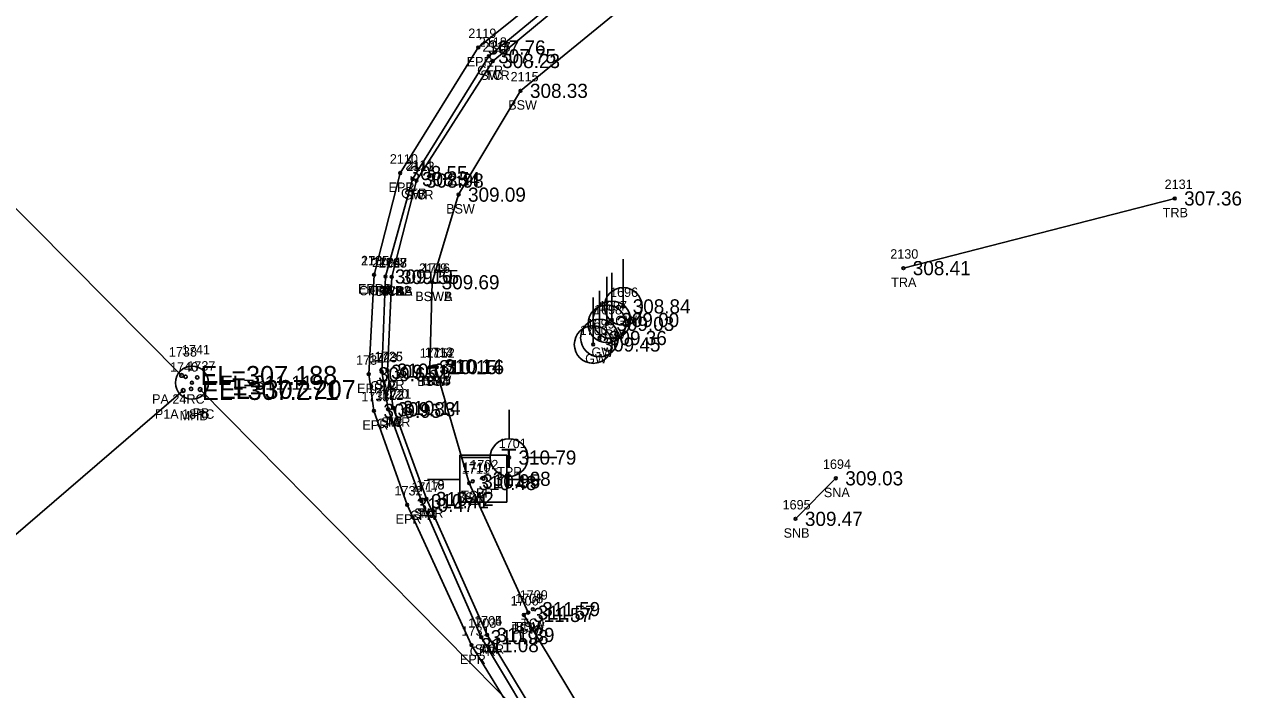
# Model space of a CAD drawing. Extents: x 1970076 to 1971136, y 803126 to 804215.
# Drawn here: x 1970647.9 to 1970777.2, y 803516.5 to 803587.1 of the extents above; entities that cross this region are included whole.
import ezdxf

# ---------------------------------------------------------------- set-up
doc = ezdxf.new("R2010")
doc.units = 0
for name, color, linetype in [('RD_EX_BldgApp', 7, 'Continuous'), ('RD_EX_BldgApp_txCode', 7, 'Continuous'), ('RD_EX_Conc', 7, 'Continuous'), ('RD_EX_Conc_txCode', 7, 'Continuous'), ('RD_EX_DR_Inlet', 7, 'Continuous'), ('RD_EX_DR_Inlet_txCode', 7, 'Continuous'), ('RD_EX_DR_Pipe', 7, 'Continuous'), ('RD_EX_DR_Pipe_txCode', 7, 'Continuous'), ('RD_EX_Road', 7, 'Continuous'), ('RD_EX_Road_txCode', 7, 'Continuous'), ('RD_EX_TX_BldgApp_ELEV', 7, 'Continuous'), ('RD_EX_TX_Conc_ELEV', 7, 'Continuous'), ('RD_EX_TX_DR_Inlet_ELEV', 7, 'Continuous'), ('RD_EX_TX_Road_ELEV', 7, 'Continuous'), ('RD_EX_TX_UT_ELEV', 7, 'Continuous'), ('RD_EX_TX_VEG_ELEV', 7, 'Continuous'), ('RD_EX_UT', 7, 'Continuous'), ('RD_EX_UT_txCode', 7, 'Continuous'), ('RD_EX_VEG', 7, 'Continuous'), ('RD_EX_VEG_txCode', 7, 'Continuous'), ('RD_HC_Survey_ELEV', 7, 'Continuous'), ('RD_SMD_Locator', 7, 'Continuous'), ('RD_TX_Pipe_ElevEX', 7, 'Continuous')]:
    doc.layers.add(name, color=color, linetype=linetype)

msp = doc.modelspace()

# ---------------------------------------------------------------- linework, layer by layer
at = {"layer": 'RD_EX_BldgApp'}
msp.add_line((1970733.96, 803538.93), (1970729.68, 803534.63), dxfattribs=at)
at = {"layer": 'RD_EX_Conc'}
for points in [[(1970686.21, 803560.33), (1970689.09, 803570.66), (1970697.16, 803583.69), (1970713.44, 803597.13), (1970734.87, 803609.74), (1970825.69, 803649.6), (1970830.95, 803651.58)], [(1970686.87, 803560.28), (1970689.49, 803570.5), (1970697.58, 803583.18), (1970713.81, 803596.63), (1970735.37, 803609.4), (1970825.99, 803648.95), (1970831.2, 803650.84)], [(1970691.16, 803559.72), (1970693.96, 803569.01), (1970700.53, 803580.02), (1970716.15, 803592.81), (1970737.19, 803605.29), (1970827.17, 803644.49), (1970832.63, 803646.72), (1970831.2, 803650.84)], [(1970714.25, 803495.32), (1970705.81, 803506.24), (1970696.37, 803522.08), (1970690.03, 803536.51), (1970686.48, 803546.25), (1970685.81, 803550.23), (1970686.21, 803560.33)], [(1970717.93, 803498.84), (1970714.88, 803495.79), (1970706.38, 803506.76), (1970696.99, 803522.32), (1970690.55, 803536.74), (1970687.04, 803546.39), (1970686.42, 803550.35), (1970686.87, 803560.28)], [(1970717.93, 803498.84), (1970710.12, 803509.16), (1970700.87, 803524.44), (1970701.35, 803524.69), (1970695.08, 803538.43), (1970691.46, 803550.8), (1970690.9, 803550.72), (1970691.16, 803559.72)]]:
    msp.add_lwpolyline(points, dxfattribs=at)
at = {"layer": 'RD_EX_DR_Inlet'}
for centre, radius in [((1970665.69, 803549.07), 1.75), ((1970665.02, 803549.7), 0.175), ((1970666.25, 803549.63), 0.175), ((1970665.6, 803548.41), 0.175)]:
    msp.add_circle(centre, radius, dxfattribs=at)
at = {"layer": 'RD_EX_DR_Pipe'}
for p, q in [((1970664.59, 803549.84), (1970592.03, 803622.94)), ((1970664.76, 803548.24), (1970617.11, 803507.28)), ((1970716.92, 803497.39), (1970666.55, 803548.35))]:
    msp.add_line(p, q, dxfattribs=at)
at = {"layer": 'RD_EX_Road'}
msp.add_lwpolyline([(1970707.08, 803502.25), (1970704.83, 803505.7), (1970695.33, 803521.24), (1970688.51, 803536.11), (1970684.99, 803546.09), (1970684.43, 803549.97), (1970685, 803560.52), (1970685, 803560.52), (1970687.77, 803571.3), (1970696.05, 803584.62), (1970712.98, 803598.27), (1970734.15, 803610.93), (1970825.09, 803650.42), (1970830.48, 803652.5), (1970835.31, 803654.39), (1970843.69, 803657.88), (1970848.64, 803660), (1970849.95, 803660.12), (1970917.12, 803684.38)], dxfattribs=at)
at = {"layer": 'RD_EX_UT'}
for p, q in [((1970711.42, 803557.16), (1970711.42, 803562.16)), ((1970710.21, 803555.72), (1970710.21, 803560.72)), ((1970709.69, 803555.31), (1970709.69, 803560.31)), ((1970708.23, 803553.12), (1970708.23, 803558.12)), ((1970708.9, 803553.81), (1970708.9, 803558.81)), ((1970699.31, 803546.2), (1970699.31, 803543.13)), ((1970699.08, 803541.39), (1970694.08, 803541.39)), ((1970694.08, 803541.39), (1970694.08, 803536.39)), ((1970699.08, 803536.39), (1970699.08, 803541.39)), ((1970694.38, 803541.15), (1970697.31, 803541.15)), ((1970701.31, 803541.15), (1970704.38, 803541.15)), ((1970690.65, 803538.82), (1970694.12, 803538.82)), ((1970699.01, 803538.82), (1970702.65, 803538.82)), ((1970694.08, 803536.39), (1970699.08, 803536.39))]:
    msp.add_line(p, q, dxfattribs=at)
for centre in [(1970711.42, 803557.16), (1970709.69, 803555.31), (1970710.21, 803555.72), (1970708.9, 803553.81), (1970708.23, 803553.12), (1970699.31, 803541.13)]:
    msp.add_circle(centre, 2, dxfattribs=at)
at = {"layer": 'RD_EX_VEG'}
msp.add_line((1970741.12, 803561.22), (1970769.89, 803568.61), dxfattribs=at)
at = {"layer": 'RD_SMD_Locator'}
for centre, radius in [((1970696.05, 803584.62), 0.15), ((1970697.16, 803583.69), 0.15), ((1970697.58, 803583.18), 0.15), ((1970697.58, 803583.18), 0.15), ((1970700.53, 803580.02), 0.15), ((1970687.77, 803571.3), 0.15), ((1970689.09, 803570.66), 0.15), ((1970689.49, 803570.5), 0.15), ((1970689.49, 803570.5), 0.15), ((1970693.96, 803569.01), 0.15), ((1970769.89, 803568.61), 0.15), ((1970685, 803560.52), 0.15), ((1970685, 803560.52), 0.15), ((1970741.12, 803561.22), 0.15), ((1970686.21, 803560.33), 0.15), ((1970686.21, 803560.33), 0.15), ((1970686.87, 803560.28), 0.15), ((1970686.87, 803560.28), 0.15), ((1970686.87, 803560.28), 0.15), ((1970686.87, 803560.28), 0.15), ((1970691.16, 803559.72), 0.15), ((1970691.16, 803559.72), 0.15), ((1970711.42, 803557.16), 0.15), ((1970709.69, 803555.31), 0.15), ((1970710.21, 803555.72), 0.15), ((1970708.23, 803553.12), 0.15), ((1970708.9, 803553.81), 0.15), ((1970685.81, 803550.23), 0.15), ((1970686.42, 803550.35), 0.15), ((1970686.42, 803550.35), 0.15), ((1970690.9, 803550.72), 0.15), ((1970691.46, 803550.8), 0.15), ((1970691.46, 803550.8), 0.15), ((1970691.65, 803550.73), 0.15), ((1970664.59, 803549.84), 0.2), ((1970665.69, 803549.07), 0.15), ((1970684.43, 803549.97), 0.15), ((1970664.76, 803548.24), 0.2), ((1970666.55, 803548.35), 0.2), ((1970686.48, 803546.25), 0.15), ((1970687.04, 803546.39), 0.15), ((1970687.04, 803546.39), 0.15), ((1970684.99, 803546.09), 0.15), ((1970699.31, 803541.13), 0.15), ((1970695.47, 803538.61), 0.15), ((1970696.59, 803538.88), 0.15), ((1970733.96, 803538.93), 0.15), ((1970695.08, 803538.43), 0.15), ((1970688.51, 803536.11), 0.15), ((1970690.03, 803536.51), 0.15), ((1970690.55, 803536.74), 0.15), ((1970690.55, 803536.74), 0.15), ((1970729.68, 803534.63), 0.15), ((1970700.87, 803524.44), 0.15), ((1970701.35, 803524.69), 0.15), ((1970701.35, 803524.69), 0.15), ((1970701.83, 803525.06), 0.15), ((1970696.37, 803522.08), 0.15), ((1970696.99, 803522.32), 0.15), ((1970696.99, 803522.32), 0.15), ((1970695.33, 803521.24), 0.15)]:
    msp.add_circle(centre, radius, dxfattribs=at)

# ---------------------------------------------------------------- texts
at = {"layer": 'RD_EX_BldgApp_txCode'}
for s, p in [('1694', (1970732.59, 803539.93)), ('SNA', (1970732.69, 803536.93)), ('1695', (1970728.31, 803535.63)), ('SNB', (1970728.42, 803532.63))]:
    msp.add_text(s, height=1, dxfattribs=at).set_placement(p)
at = {"layer": 'RD_EX_Conc_txCode'}
for s, p in [('2118', (1970696.1, 803584.69)), ('2116', (1970696.49, 803584.18)), ('2117', (1970696.51, 803584.18)), ('CFR', (1970695.93, 803581.69)), ('SWR', (1970696.26, 803581.18)), ('TC', (1970696.78, 803581.18)), ('2115', (1970699.47, 803581.02)), ('BSW', (1970699.22, 803578.02)), ('2111', (1970688.31, 803571.66)), ('2112', (1970688.43, 803571.5)), ('2113', (1970688.43, 803571.5)), ('2114', (1970692.9, 803570.01)), ('CFR', (1970687.86, 803568.66)), ('SWR', (1970688.18, 803568.5)), ('TC', (1970688.7, 803568.5)), ('BSW', (1970692.64, 803567.01)), ('2106', (1970684.8, 803561.33)), ('1724', (1970684.86, 803561.33)), ('2107', (1970685.48, 803561.28)), ('2108', (1970685.48, 803561.28)), ('1727', (1970685.52, 803561.28)), ('1728', (1970685.52, 803561.28)), ('2109', (1970689.77, 803560.72)), ('1716', (1970690.07, 803560.72)), ('CFRA 12', (1970683.39, 803558.33)), ('CFRB', (1970684.51, 803558.33)), ('SWRA', (1970685.06, 803558.28)), ('SWRB', (1970685.08, 803558.28)), ('TCA', (1970685.58, 803558.28)), ('TCB', (1970685.6, 803558.28)), ('BSWA', (1970689.36, 803557.72)), ('BSWB', (1970689.37, 803557.72)), ('1713', (1970690.39, 803551.8)), ('1714', (1970690.39, 803551.8)), ('1723', (1970684.47, 803551.23)), ('1726', (1970685.05, 803551.35)), ('1725', (1970685.08, 803551.35)), ('1715', (1970689.84, 803551.72)), ('1712', (1970690.58, 803551.73)), ('CFR', (1970684.58, 803548.23)), ('SWR', (1970685.11, 803548.35)), ('TC', (1970685.63, 803548.35)), ('BSW', (1970689.58, 803548.72)), ('TC4B', (1970689.74, 803548.8)), ('BSW', (1970690.14, 803548.8)), ('TC4', (1970690.4, 803548.73)), ('1722', (1970685.14, 803547.25)), ('1720', (1970685.66, 803547.39)), ('1721', (1970685.98, 803547.39)), ('CFR', (1970685.26, 803544.25)), ('SWR', (1970685.73, 803544.39)), ('TC', (1970686.25, 803544.39)), ('1711', (1970694.3, 803539.43)), ('1710', (1970694.37, 803539.61)), ('1718', (1970689.49, 803537.74)), ('1719', (1970689.49, 803537.74)), ('1717', (1970688.96, 803537.51)), ('BSW', (1970693.76, 803536.43)), ('TC4', (1970694.23, 803536.61)), ('CFR', (1970688.8, 803534.51)), ('SWR', (1970689.24, 803534.74)), ('TC', (1970689.76, 803534.74)), ('1709', (1970700.44, 803526.06)), ('1706', (1970699.47, 803525.44)), ('1707', (1970699.96, 803525.69)), ('1708', (1970699.96, 803525.69)), ('1703', (1970694.98, 803523.08)), ('1704', (1970695.6, 803523.32)), ('1705', (1970695.6, 803523.32)), ('TC4A', (1970699.61, 803522.69)), ('BSW', (1970699.56, 803522.44)), ('BSW', (1970700.03, 803522.69)), ('TC4', (1970700.58, 803523.06)), ('CFR', (1970695.14, 803520.08)), ('SWR', (1970695.67, 803520.32)), ('TC', (1970696.19, 803520.32))]:
    msp.add_text(s, height=1, dxfattribs=at).set_placement(p)
at = {"layer": 'RD_EX_DR_Inlet_txCode'}
for s, p in [('1741', (1970664.62, 803552.07)), ('MHD', (1970664.39, 803545.07))]:
    msp.add_text(s, height=1, dxfattribs=at).set_placement(p)
at = {"layer": 'RD_EX_DR_Pipe_txCode'}
for s, p in [('1738', (1970663.24, 803551.84)), ('1740', (1970663.37, 803550.24)), ('1737', (1970665.2, 803550.35)), ('PA 24RC', (1970661.46, 803546.84)), ('PB', (1970665.77, 803545.35)), ('P1A 18RC', (1970661.75, 803545.24))]:
    msp.add_text(s, height=1, dxfattribs=at).set_placement(p)
at = {"layer": 'RD_EX_Road_txCode'}
for s, p in [('2119', (1970694.99, 803585.62)), ('EPR', (1970694.82, 803582.62)), ('2110', (1970686.67, 803572.3)), ('EPR', (1970686.54, 803569.3)), ('2105', (1970683.61, 803561.52)), ('1735', (1970683.65, 803561.52)), ('EPRA', (1970683.28, 803558.52)), ('EPRB', (1970683.3, 803558.52)), ('1734', (1970683.09, 803550.97)), ('EPR', (1970683.2, 803547.97)), ('1733', (1970683.65, 803547.09)), ('EPR', (1970683.76, 803544.09)), ('1732', (1970687.16, 803537.11)), ('EPR', (1970687.28, 803534.11)), ('1731', (1970694.27, 803522.24)), ('EPR', (1970694.1, 803519.24))]:
    msp.add_text(s, height=1, dxfattribs=at).set_placement(p)
at = {"layer": 'RD_EX_TX_BldgApp_ELEV'}
for s, p in [('309.03', (1970734.96, 803538.18)), ('309.47', (1970730.68, 803533.88))]:
    msp.add_text(s, height=1.5, dxfattribs=at).set_placement(p)
at = {"layer": 'RD_EX_TX_Conc_ELEV'}
for s, p in [('307.75', (1970698.16, 803582.94)), ('308.23', (1970698.58, 803582.43)), ('308.23', (1970698.58, 803582.43)), ('308.33', (1970701.53, 803579.27)), ('308.54', (1970690.09, 803569.91)), ('308.98', (1970690.49, 803569.75)), ('308.98', (1970690.49, 803569.75)), ('309.09', (1970694.96, 803568.26)), ('309.10', (1970687.21, 803559.58)), ('309.10', (1970687.21, 803559.58)), ('309.55', (1970687.87, 803559.53)), ('309.55', (1970687.87, 803559.53)), ('309.55', (1970687.87, 803559.53)), ('309.55', (1970687.87, 803559.53)), ('309.69', (1970692.16, 803558.97)), ('309.69', (1970692.16, 803558.97)), ('310.14', (1970692.46, 803550.05)), ('310.14', (1970692.46, 803550.05)), ('309.61', (1970686.81, 803549.48)), ('310.07', (1970687.42, 803549.6)), ('310.07', (1970687.42, 803549.6)), ('310.15', (1970691.9, 803549.97)), ('310.16', (1970692.65, 803549.98)), ('309.83', (1970687.48, 803545.5)), ('310.14', (1970688.04, 803545.64)), ('310.14', (1970688.04, 803545.64)), ('310.48', (1970696.08, 803537.68)), ('310.95', (1970696.47, 803537.86)), ('310.42', (1970691.55, 803535.99)), ('310.42', (1970691.55, 803535.99)), ('310.41', (1970691.03, 803535.76)), ('311.59', (1970702.83, 803524.31)), ('311.57', (1970701.87, 803523.69)), ('311.57', (1970702.35, 803523.94)), ('311.57', (1970702.35, 803523.94)), ('311.39', (1970697.99, 803521.57)), ('311.39', (1970697.99, 803521.57)), ('310.98', (1970697.37, 803521.33))]:
    msp.add_text(s, height=1.5, dxfattribs=at).set_placement(p)
at = {"layer": 'RD_EX_TX_DR_Inlet_ELEV'}
msp.add_text('EL=311.119', height=1.5, dxfattribs=at).set_placement((1970668.69, 803548.32))
at = {"layer": 'RD_EX_TX_Road_ELEV'}
for s, p in [('307.76', (1970697.05, 803583.87)), ('308.55', (1970688.77, 803570.55)), ('309.09', (1970686, 803559.77)), ('309.09', (1970686, 803559.77)), ('309.65', (1970685.43, 803549.22)), ('309.95', (1970685.99, 803545.34)), ('310.47', (1970689.51, 803535.36)), ('311.08', (1970696.33, 803520.49))]:
    msp.add_text(s, height=1.5, dxfattribs=at).set_placement(p)
at = {"layer": 'RD_EX_TX_UT_ELEV'}
for s, p in [('308.84', (1970712.42, 803556.41)), ('309.03', (1970710.69, 803554.56)), ('309.00', (1970711.21, 803554.97)), ('309.36', (1970709.9, 803553.06)), ('309.45', (1970709.23, 803552.37)), ('310.79', (1970700.31, 803540.38))]:
    msp.add_text(s, height=1.5, dxfattribs=at).set_placement(p)
at = {"layer": 'RD_EX_TX_VEG_ELEV'}
for s, p in [('307.36', (1970770.89, 803567.86)), ('308.41', (1970742.12, 803560.47))]:
    msp.add_text(s, height=1.5, dxfattribs=at).set_placement(p)
at = {"layer": 'RD_EX_UT'}
msp.add_text('T', height=2, dxfattribs=at).set_placement((1970698.47, 803540.08))
at = {"layer": 'RD_EX_UT_txCode'}
for s, p in [('1696', (1970710.02, 803558.16)), ('1698', (1970708.32, 803556.31)), ('1697', (1970708.84, 803556.72)), ('1699', (1970707.53, 803554.81)), ('GW', (1970710.57, 803555.16)), ('1700', (1970706.8, 803554.12)), ('GW', (1970708.85, 803553.31)), ('GW', (1970709.37, 803553.72)), ('GW', (1970708.05, 803551.81)), ('GW', (1970707.38, 803551.12)), ('1701', (1970698.21, 803542.13)), ('1702', (1970695.2, 803539.88)), ('TPP', (1970698.05, 803539.13)), ('PP', (1970695.81, 803536.88))]:
    msp.add_text(s, height=1, dxfattribs=at).set_placement(p)
at = {"layer": 'RD_EX_VEG_txCode'}
for s, p in [('2131', (1970768.82, 803569.61)), ('TRB', (1970768.62, 803566.61)), ('2130', (1970739.73, 803562.22)), ('TRA', (1970739.83, 803559.22))]:
    msp.add_text(s, height=1, dxfattribs=at).set_placement(p)
at = {"layer": 'RD_HC_Survey_ELEV'}
msp.add_text('311.08', height=1.5, dxfattribs=at).set_placement((1970697.59, 803538.13))
at = {"layer": 'RD_TX_Pipe_ElevEX'}
for s, p in [('EL=307.188', (1970666.59, 803548.84)), ('EL=307.271', (1970666.76, 803547.24)), ('EL=307.207', (1970668.55, 803547.35))]:
    msp.add_text(s, height=2, dxfattribs=at).set_placement(p)

doc.saveas('drawing.dxf')
